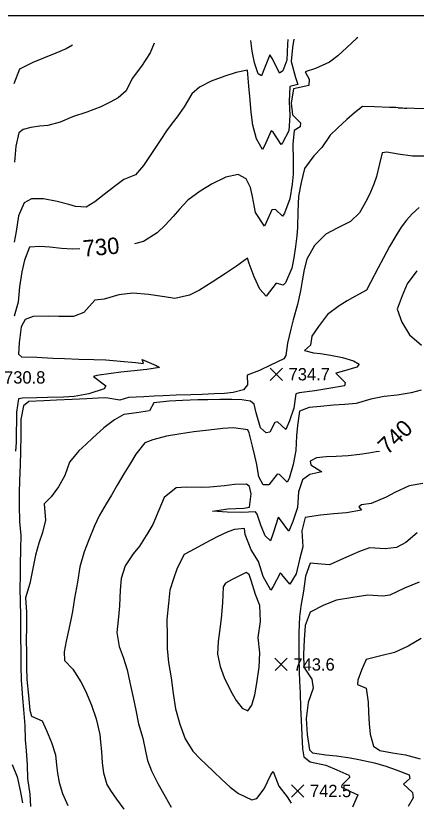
# Model space of a CAD drawing. Extents: x 2566079 to 2571326, y 424054 to 426896.
# Drawn here: x 2570104 to 2570592, y 425917 to 426874 of the extents above; entities that cross this region are included whole.
import ezdxf

# ---------------------------------------------------------------- set-up
doc = ezdxf.new("R2010")
doc.units = 0
for name, color, linetype in [('Contour_ADS_Label_Major', 7, 'Continuous'), ('Contour_ADS_Major', 7, 'Continuous'), ('Contour_ADS_Minor', 7, 'Continuous'), ('Contour_ADS_Spot_Elevation', 7, 'Continuous'), ('Contour_ADS_State_Plane_Border', 7, 'Continuous')]:
    doc.layers.add(name, color=color, linetype=linetype)

# ---------------------------------------------------------------- blocks, each defined once
blk = doc.blocks.new('S750')
at = {"layer": 'Contour_ADS_Spot_Elevation'}
for p, q in [((-0.5, 0.498), (0.5, -0.498)), ((-0.498, -0.5), (0.498, 0.5))]:
    blk.add_line(p, q, dxfattribs=at)

msp = doc.modelspace()

# ---------------------------------------------------------------- linework, layer by layer
at = {"layer": 'Contour_ADS_Major'}
for points in [[(2570520.61, 426847.17), (2570519.03, 426845.86), (2570507.03, 426834.96), (2570496.2, 426825.13), (2570486.28, 426817.4), (2570469.13, 426809.65), (2570456.51, 426805.54), (2570461.22, 426796.51), (2570460.75, 426788.8), (2570442.16, 426784.88), (2570439.63, 426767.36), (2570440.91, 426753.06), (2570450.82, 426743.52), (2570450.24, 426738.77), (2570442.94, 426734.14), (2570441.35, 426717.6), (2570442.02, 426697.77), (2570441.98, 426681.08), (2570440.61, 426668.8), (2570437.85, 426650.87), (2570431.33, 426633.6), (2570428.76, 426629.98), (2570420.45, 426637.81), (2570415.95, 426637.6), (2570409.22, 426622.35), (2570406.82, 426617.78), (2570396.14, 426634.25), (2570392.43, 426653.8), (2570389.93, 426664.76), (2570384.76, 426675.15), (2570375.07, 426680.41), (2570360.06, 426677.47), (2570343.11, 426669.33), (2570328.65, 426660.5), (2570313.86, 426649.16), (2570303.58, 426638.52), (2570295.7, 426629.48), (2570286.12, 426618.95), (2570276.22, 426609.43), (2570259.72, 426599.01), (2570248.64, 426596.14)], [(2570182.24, 426590.11), (2570173.16, 426589.78), (2570160.13, 426590.62), (2570145.89, 426592.02), (2570133.52, 426593.13), (2570120.92, 426592.31), (2570114.9, 426576.21), (2570111.65, 426562.07), (2570108.86, 426543.87), (2570107.12, 426525.37), (2570102.32, 426508.18)], [(2570547.06, 426343.62), (2570542.76, 426343.27), (2570533.8, 426341.53), (2570522.9, 426339.75), (2570508.94, 426338.41), (2570494.22, 426337.5), (2570481.89, 426336.92), (2570470.09, 426336.02), (2570462.72, 426331.75), (2570463.2, 426327.38), (2570476.92, 426318.85), (2570462.07, 426315.68), (2570453.32, 426309.05), (2570448.54, 426294.43), (2570447.15, 426275.55), (2570441.36, 426258.47), (2570436.54, 426246.48), (2570425.42, 426262), (2570423.61, 426263.14), (2570417.53, 426244.39), (2570414.47, 426235.08), (2570407.81, 426240.93), (2570402.44, 426253.94), (2570398, 426267.52), (2570396.23, 426269.98), (2570379.01, 426269.3), (2570361.55, 426269.7), (2570343.64, 426270.81), (2570362.54, 426273.62), (2570381.88, 426274.75), (2570388.81, 426275.65), (2570390.68, 426291.93), (2570388.9, 426301.1), (2570385.09, 426303.89), (2570370.46, 426303.52), (2570358.27, 426301.94), (2570340.32, 426300.27), (2570329.9, 426299.91), (2570311.76, 426300.19), (2570299.55, 426299.34), (2570284.94, 426287.74), (2570278.4, 426272.17), (2570270.95, 426254.91), (2570265.05, 426244.67), (2570255.07, 426228.37), (2570247.29, 426218.95), (2570237.36, 426204.38), (2570232.45, 426189.09), (2570231.41, 426175.04), (2570230.71, 426155.78), (2570229.16, 426142.46), (2570227.41, 426123.19), (2570229.93, 426106.25), (2570235.11, 426093.18), (2570239.69, 426078.14), (2570242.95, 426062.39), (2570247.19, 426044.47), (2570250.35, 426029.05), (2570253.66, 426012.07), (2570259.01, 425994.74), (2570262.54, 425977.01), (2570264.73, 425967.55), (2570269.32, 425955.14), (2570277.03, 425939.66), (2570285.96, 425923.78), (2570293.55, 425910.88)]]:
    msp.add_lwpolyline(points, dxfattribs=at)
at = {"layer": 'Contour_ADS_Minor'}
for points in [[(2570780.48, 426854.17), (2570780.38, 426851.3), (2570779.9, 426837.39), (2570779.42, 426818.72), (2570778.35, 426800.91), (2570772.67, 426783.42), (2570767.53, 426775.59), (2570757.18, 426779.14), (2570751.98, 426773.98), (2570744.94, 426773.59), (2570735.77, 426784.36), (2570728.02, 426795.99), (2570720.41, 426800.62), (2570704.04, 426797.08), (2570686.02, 426794.85), (2570669.4, 426792.1), (2570659.08, 426789.79), (2570648.35, 426787.36), (2570637.98, 426785.03), (2570621.88, 426778.83), (2570613.03, 426761.83), (2570598.23, 426760.6), (2570580.19, 426761.28)], [(2570442.52, 426845.07), (2570441.04, 426834.99), (2570439.57, 426817.88), (2570444.54, 426798.67), (2570447.46, 426790.19), (2570437.86, 426787.58), (2570436.88, 426769.28), (2570437.74, 426752.17), (2570436.59, 426733.56), (2570429.08, 426719), (2570427.12, 426716.95), (2570417.61, 426732.13), (2570414.98, 426733.53), (2570407.12, 426715.49), (2570404.69, 426710.84), (2570397.28, 426723.85), (2570392.81, 426740.69), (2570390.76, 426756.51), (2570389.14, 426775.61), (2570388.07, 426787.85), (2570386.24, 426807.64), (2570372.46, 426804.57), (2570358.57, 426800.25), (2570342.27, 426794.18), (2570327.83, 426786.81), (2570318.48, 426778.65), (2570309.3, 426762.99), (2570300.53, 426750.56), (2570294.71, 426743.14), (2570287.85, 426733.58), (2570280.83, 426723.22), (2570270.48, 426707.23), (2570259.54, 426691.54), (2570249.82, 426680.17), (2570235.75, 426674.41), (2570224.52, 426666.15), (2570211.7, 426656.13), (2570200.53, 426647.49), (2570189.81, 426640.7), (2570177.14, 426641.72), (2570168.73, 426644.07), (2570154.58, 426647.89), (2570138, 426651.11), (2570123.46, 426651.08), (2570114.34, 426646.09), (2570107.66, 426630.11), (2570104.77, 426611.42), (2570102.21, 426598.45)], [(2570435.42, 426844.88), (2570435.09, 426839.11), (2570434.1, 426819.58), (2570429.5, 426806.5), (2570425.28, 426803.83), (2570416.76, 426821.49), (2570413.42, 426826.18), (2570407.18, 426809.76), (2570403.21, 426800.66), (2570399.47, 426803.08), (2570394.63, 426816.33), (2570391.94, 426830.71), (2570390.41, 426843.66)], [(2570173.27, 426837.82), (2570165.59, 426833.65), (2570152.98, 426828.38), (2570138.06, 426822.11), (2570124.93, 426816.66), (2570108.97, 426808.71), (2570101.79, 426791.01)], [(2570272.62, 426840.49), (2570267.91, 426828.44), (2570257.43, 426812.3), (2570245.78, 426797.32), (2570238.81, 426782.38), (2570228.85, 426773.88), (2570218.98, 426768.38), (2570207.68, 426762.88), (2570190.96, 426756.36), (2570173.42, 426750.8), (2570158.35, 426744.1), (2570143.15, 426740.1), (2570133.63, 426739.23), (2570122.77, 426737.77), (2570113.46, 426735.24), (2570107.91, 426731.33), (2570104.36, 426715.06), (2570102.83, 426695.65)], [(2570559.09, 426762.26), (2570541.01, 426763.09), (2570526.16, 426763.33), (2570516.72, 426755.59), (2570507.33, 426747.38), (2570496.35, 426737.53), (2570487.08, 426728.53), (2570476.6, 426713.6), (2570466.9, 426703.37), (2570455.61, 426687.96), (2570451.46, 426670.67), (2570448.29, 426654.24), (2570447.48, 426635.53), (2570447.3, 426616.24), (2570446.22, 426606.1), (2570444.69, 426593.04), (2570442.72, 426579.05), (2570440.28, 426566.67), (2570432.48, 426548.93), (2570429.86, 426545.9), (2570421.17, 426548.43), (2570409.16, 426532.67), (2570401.42, 426541.12), (2570394.32, 426556.1), (2570388.44, 426572.4), (2570386.27, 426578.62), (2570372.82, 426569.12), (2570359.62, 426560.12), (2570343.46, 426549.49), (2570327.86, 426540.03), (2570315.64, 426533.9), (2570297.79, 426529.71), (2570285.15, 426531.78), (2570265.97, 426534.78), (2570246.79, 426536.21), (2570229.91, 426534.03), (2570211.98, 426528.76), (2570200.42, 426527.54), (2570186.98, 426512.88), (2570174.42, 426507.84), (2570156.5, 426507.7), (2570143.85, 426508.08), (2570125.37, 426507.94), (2570115.62, 426504.18), (2570110.9, 426495.12), (2570108.29, 426475.87), (2570107.77, 426461.96), (2570111.32, 426458.86), (2570129.75, 426458.15), (2570149.59, 426457.31), (2570163.69, 426456.72), (2570181.2, 426456.1), (2570199.15, 426455.5), (2570213.76, 426455.01), (2570231.83, 426453.67), (2570249.87, 426451.66), (2570259.56, 426450.52), (2570258.18, 426455.3), (2570275.25, 426448.13), (2570279.33, 426445.85), (2570263.71, 426443.41), (2570244.45, 426441.32), (2570232.33, 426439.97), (2570220.56, 426438.61), (2570203.12, 426436.2), (2570198.92, 426435.02), (2570213.89, 426423.39), (2570211.7, 426419.9), (2570193.3, 426413.92), (2570175.39, 426410.46), (2570162.31, 426409.76), (2570142.75, 426409.18), (2570129.93, 426408.84), (2570112.65, 426408.38), (2570107.43, 426407.7), (2570105.33, 426391.58), (2570105.19, 426380.28), (2570104.94, 426367.04), (2570104.58, 426354.36), (2570104.05, 426343.88)], [(2570604.42, 426702.74), (2570587.09, 426702.97), (2570569.79, 426705.31), (2570555.69, 426707.8), (2570550.24, 426706.75), (2570546.95, 426693.54), (2570543.23, 426678.19), (2570540.12, 426668.94), (2570536.13, 426659.24), (2570531.62, 426649.75), (2570522.63, 426634.07), (2570511.63, 426623.33), (2570495.25, 426615.18), (2570481.65, 426607.94), (2570467.82, 426594.3), (2570458.57, 426577.53), (2570455.3, 426564.96), (2570452.89, 426551.37), (2570450.95, 426539.2), (2570447.14, 426522.58), (2570442, 426503.79), (2570439.13, 426492.42), (2570435.13, 426475.4), (2570433.15, 426460.48), (2570430.45, 426456.36), (2570414.42, 426448.42), (2570400.88, 426441.98), (2570385.7, 426436.48), (2570386.2, 426424.81), (2570381.55, 426418.71), (2570368.7, 426415.19), (2570358.32, 426414.23), (2570345.65, 426413.58), (2570331.32, 426413.06), (2570317.39, 426412.65), (2570299.59, 426412.17), (2570283.63, 426411.41), (2570272.78, 426410.84), (2570260.11, 426410.17), (2570241.61, 426409.19), (2570231.02, 426406.12), (2570213.83, 426408.77), (2570204.37, 426408.37), (2570190.75, 426407.64), (2570172.87, 426406.75), (2570154.04, 426405.86), (2570138.4, 426405.15), (2570120.01, 426404.35), (2570113.79, 426399.19), (2570110.54, 426382.32), (2570110.34, 426363.12), (2570110, 426343.77), (2570109.55, 426327.18), (2570108.67, 426308.39), (2570108.42, 426293.2), (2570108.44, 426277.76), (2570108.87, 426258.36), (2570110.35, 426241.42), (2570110.11, 426225.18), (2570109.68, 426205.29), (2570109.52, 426191.75), (2570109.44, 426178.01), (2570109.56, 426159.93), (2570109.96, 426144.66), (2570110.02, 426134.69), (2570110.16, 426118.15), (2570110.34, 426099.09), (2570110.49, 426082.89), (2570110.86, 426065.25), (2570111.65, 426055.11), (2570112.52, 426043.44), (2570113.55, 426029.8), (2570115.18, 426010.32), (2570115.85, 425992.65), (2570116.94, 425979.77), (2570118.15, 425962.34)], [(2570595.24, 426640.25), (2570586.75, 426632.55), (2570579.65, 426624.94), (2570573.29, 426616.51), (2570566.69, 426606.03), (2570559.21, 426592.88), (2570551.65, 426579), (2570545.15, 426566.93), (2570535.82, 426549.25), (2570531.29, 426539.81), (2570517.04, 426532.08), (2570507.71, 426526.89), (2570497.67, 426520.76), (2570483.86, 426510.19), (2570472.87, 426495.73), (2570464.73, 426483.87), (2570463.12, 426472.89), (2570455.61, 426466.5), (2570466.78, 426463.59), (2570475.31, 426462.71), (2570487.17, 426460.85), (2570501.82, 426457.76), (2570515.12, 426453.88), (2570522.05, 426449.79), (2570519.32, 426446.05), (2570501.53, 426440.73), (2570493.82, 426438.97), (2570505.21, 426427.65), (2570504.17, 426423.43), (2570485.46, 426420.24), (2570468.19, 426417.33), (2570449.25, 426414.75), (2570445.24, 426413.6), (2570442.67, 426396.46), (2570437.57, 426380.74), (2570432.99, 426370.17), (2570422.97, 426379.73), (2570419.75, 426378.99), (2570413.3, 426366.9), (2570408.96, 426366.46), (2570402.14, 426372.32), (2570396.89, 426390.58), (2570394.22, 426401.07), (2570389.87, 426404.98), (2570379.48, 426406.39), (2570367.37, 426406.67), (2570352.5, 426406.68), (2570337.89, 426406.54), (2570325.87, 426406.35), (2570307.24, 426405.77), (2570290.8, 426404.87), (2570272.27, 426402.96), (2570267.2, 426393.03), (2570251.07, 426390.75), (2570235.97, 426388.57), (2570224.56, 426382.11), (2570211.42, 426372.47), (2570197.76, 426359.81), (2570189.8, 426352.65), (2570180.95, 426344.42), (2570169.51, 426330.46), (2570164.14, 426314.23), (2570156.49, 426300.76), (2570147.37, 426288.36), (2570138.8, 426279.72), (2570140.34, 426259.85), (2570136.88, 426244.98), (2570132.25, 426232.18)], [(2570592.2, 426563.46), (2570580.71, 426547.41), (2570574.59, 426533.1), (2570568.58, 426516.82), (2570574.24, 426501.07), (2570583.62, 426485.61), (2570597.95, 426473.04)], [(2570597.82, 426418.23), (2570585.65, 426414.87), (2570568.45, 426411.97), (2570552.65, 426410.48), (2570536.49, 426407.44), (2570518.69, 426401.99), (2570504.92, 426400.85), (2570490.97, 426399.75), (2570475.09, 426398.39), (2570461.53, 426397.06), (2570449.71, 426392.68), (2570446.96, 426375.4), (2570445.93, 426362.7), (2570444.95, 426344.78), (2570441.68, 426327.93), (2570436.93, 426310.72), (2570434.73, 426306.1), (2570425.37, 426315.45), (2570422.31, 426316.09), (2570412.32, 426302.83), (2570405.41, 426302.88), (2570400.15, 426312.61), (2570397.49, 426327.9), (2570395.15, 426338.33), (2570392.46, 426349.93), (2570388.44, 426366.39), (2570386.62, 426369.75), (2570369.09, 426372.23), (2570356.2, 426371.42), (2570339.21, 426369.64), (2570321.02, 426367.35), (2570305.29, 426365.14), (2570287.85, 426362.13), (2570271.22, 426357.76), (2570261.38, 426354.24), (2570250.46, 426340.3), (2570243.81, 426329.55), (2570235.88, 426316.38), (2570227.83, 426302.78), (2570220.61, 426290.43), (2570214.5, 426279.9), (2570205.92, 426265.11), (2570199.96, 426253.26), (2570193.14, 426236.23), (2570187.65, 426221.34), (2570182.4, 426203.25), (2570179.22, 426184.47), (2570175.87, 426164.94), (2570173.47, 426149.08), (2570171.75, 426140.73), (2570168.85, 426127.6), (2570165.65, 426112.69), (2570163.31, 426100.03), (2570163.43, 426089.42), (2570173.63, 426078.95), (2570183.32, 426063.5), (2570189.31, 426052.2), (2570196.27, 426035.09), (2570202.08, 426018.42), (2570206.76, 425999.27), (2570207.58, 425989.89), (2570208.47, 425978.39), (2570209.62, 425964.72), (2570210.93, 425952.56), (2570215.1, 425938.38), (2570219.78, 425931.22), (2570227.08, 425920.76), (2570235.72, 425908.43)], [(2570599.72, 426304.69), (2570583.2, 426301.98), (2570565.43, 426293.65), (2570555.17, 426287.84), (2570536.69, 426280.42), (2570525.02, 426278.77), (2570521.86, 426276.35), (2570525.03, 426272.08), (2570506.7, 426269.08), (2570491.44, 426267.92), (2570475.29, 426266.23), (2570456.38, 426263.16), (2570452.59, 426247.13), (2570453.64, 426227.62), (2570449.57, 426212.32), (2570445.6, 426194.8), (2570437.74, 426182.19), (2570428.17, 426194.03), (2570425.97, 426195.72), (2570417.43, 426179.25), (2570414.71, 426174.86), (2570405.52, 426191.36), (2570399.51, 426209.75), (2570390.68, 426223.96), (2570383.57, 426242.59), (2570382.84, 426249.9), (2570370.39, 426248.79), (2570362.24, 426245.83), (2570349.46, 426239.6), (2570334.82, 426231.86), (2570322.02, 426225.04), (2570309.3, 426218.29), (2570300.67, 426201.56), (2570296.17, 426188.73), (2570291.93, 426175.01), (2570290.05, 426158.71), (2570288.33, 426139.14), (2570288.55, 426119.33), (2570288.52, 426104.05), (2570290.26, 426086.8), (2570293.38, 426068.4), (2570295.79, 426049.23), (2570298.71, 426030.68), (2570303.98, 426011.83), (2570310.55, 425994.12), (2570319.66, 425978.99), (2570329.16, 425969.16)], [(2570592.77, 426244.77), (2570578.85, 426232.9), (2570567.55, 426226.61), (2570553.8, 426225.17), (2570534.96, 426226.28), (2570522.49, 426222.11), (2570513.45, 426217.98), (2570503.09, 426213.25), (2570486.11, 426205.58), (2570471.36, 426206.8), (2570462.71, 426207.52), (2570457.04, 426191.72), (2570454.48, 426173.81), (2570451.07, 426155.58), (2570449.66, 426142.44), (2570448.66, 426123.4), (2570448.76, 426104.33), (2570448.91, 426093.45), (2570449.24, 426075.61), (2570449.65, 426064.22), (2570450.22, 426049.39), (2570450.9, 426031.85), (2570451.5, 426016.74), (2570452.41, 425998.31), (2570453.42, 425981.73), (2570454.77, 425972.03), (2570462.56, 425966.12)], [(2570132.25, 426232.18), (2570128.16, 426217.54), (2570125.02, 426201.3), (2570121.5, 426183.11), (2570116.17, 426165.66), (2570117.31, 426147.91), (2570117.27, 426129.44), (2570117.13, 426114.35), (2570117.19, 426099.11), (2570117.45, 426081.18), (2570117.94, 426066.19), (2570119.7, 426046.85), (2570121.53, 426028.97), (2570123.49, 426021.61), (2570136.42, 426015.8), (2570141.64, 426004.02), (2570147.88, 425989.45), (2570152.83, 425974.64), (2570153.98, 425961.93), (2570154.97, 425952.33), (2570157.06, 425940.69), (2570161.09, 425927.38), (2570167.47, 425913.06)], [(2570595.34, 426184.73), (2570577.27, 426177.28), (2570559.67, 426168.64), (2570550.87, 426167.62), (2570532.57, 426168.9), (2570514.33, 426165.92), (2570494.74, 426162.54), (2570479.22, 426156.59), (2570462.72, 426148.15), (2570456.4, 426132.01), (2570455.33, 426114.35), (2570454.38, 426097.02), (2570454.91, 426081.33), (2570464.69, 426066.57), (2570466.37, 426055.71), (2570460.24, 426038.29), (2570457.54, 426018.82), (2570458.83, 425999.07), (2570461.59, 425980.43), (2570465.61, 425977.07), (2570481.72, 425974.7), (2570494.63, 425973.2), (2570511.09, 425970.91), (2570521.72, 425968.88), (2570540.77, 425964.76), (2570554.47, 425960.73), (2570567.25, 425956.28), (2570583.17, 425950.18), (2570583.66, 425945.82), (2570576.34, 425938.71)], [(2570597.83, 426115.92), (2570581.64, 426106.79), (2570565.18, 426099.18), (2570548.74, 426095.06), (2570530.9, 426090.71), (2570525.1, 426077.61), (2570520.5, 426065.27), (2570520.29, 426060.28), (2570530.88, 426055.7), (2570533.25, 426038.78), (2570533.66, 426026.16), (2570534.54, 426012.09), (2570535.78, 425999.51), (2570539.65, 425985.18), (2570547.42, 425979.7), (2570562.6, 425977.06), (2570578.67, 425974.69), (2570596.34, 425969.84)], [(2570329.16, 425969.16), (2570336.02, 425962.71), (2570344.82, 425954.14), (2570354.89, 425944.46), (2570365.3, 425935.11), (2570375.22, 425927.4), (2570391.7, 425919.92), (2570397.65, 425921.26), (2570406.62, 425933.02), (2570414.5, 425950.04), (2570417.68, 425954.31), (2570424.35, 425936.27), (2570434.62, 425923.57), (2570439.52, 425915.71)], [(2570462.56, 425966.12), (2570481.49, 425961.88), (2570495.01, 425956.19), (2570509.51, 425949.62), (2570510.92, 425947.32), (2570501.23, 425937.52), (2570500.57, 425935.06), (2570517.9, 425927.08), (2570520.7, 425925.78), (2570513.95, 425910.97)], [(2570099.84, 425962.89), (2570105.83, 425947.85), (2570109.56, 425931.2), (2570112.66, 425916.27)], [(2570118.15, 425962.34), (2570118.7, 425945.62), (2570121.38, 425926.74), (2570122.21, 425911.47)], [(2570576.34, 425938.71), (2570587.26, 425928.54), (2570587.85, 425922.07), (2570581.81, 425911.8)]]:
    msp.add_lwpolyline(points, dxfattribs=at)
msp.add_lwpolyline([(2570365.88, 426052), (2570372.5, 426040.77), (2570379.91, 426031.27), (2570386.69, 426028.26), (2570391.73, 426034.88), (2570395.2, 426047.71), (2570397.56, 426061.7), (2570400.36, 426081.12), (2570401.24, 426098.63), (2570399.35, 426117.34), (2570402.05, 426136.75), (2570401.22, 426156.32), (2570396.07, 426169.73), (2570390.59, 426186.53), (2570388.39, 426194.1), (2570384.67, 426196.39), (2570367.7, 426187.8), (2570359.44, 426183.58), (2570356.66, 426179.02), (2570355.87, 426159.46), (2570354.11, 426140.39), (2570352.32, 426124.77), (2570350.65, 426112.54), (2570349.9, 426096.83), (2570352.92, 426081.9), (2570357.82, 426068.49), (2570365.88, 426052)], close=True, dxfattribs=at)
for centre, radius, start, end in [((2569450.73, 402784.74), 24003.12, 87.328175, 87.353386), ((2570682.75, 429083.26), 2324.25, 267.2106, 267.47096)]:
    msp.add_arc(centre, radius, start, end, dxfattribs=at)
at = {"layer": 'Contour_ADS_State_Plane_Border'}
msp.add_lwpolyline([(2566079.33, 424077.11), (2571302.93, 424077.11), (2571302.93, 426873.74), (2566079.33, 426873.74), (2566079.33, 424077.11)], close=True, dxfattribs=at)

# ---------------------------------------------------------------- block references
at = {"layer": 'Contour_ADS_Spot_Elevation', "xscale": 15, "yscale": 15}
for p in [(2570421.32, 426437.59), (2570427.25, 426084.51), (2570447.33, 425930.54)]:
    msp.add_blockref('S750', p, dxfattribs=at)

# ---------------------------------------------------------------- texts
at = {"layer": 'Contour_ADS_Label_Major'}
for s, rotation, p in [('730', 5.18517, (2570186.75, 426580.48)), ('740', 43.332, (2570556.54, 426338.82))]:
    msp.add_text(s, height=20, rotation=rotation, dxfattribs=at).set_placement(p)
at = {"layer": 'Contour_ADS_Spot_Elevation'}
for s, p in [('734.7', (2570436.32, 426430.09)), ('730.8', (2570090.09, 426426.26)), ('743.6', (2570442.25, 426077.01)), ('742.5', (2570462.33, 425923.04))]:
    msp.add_text(s, height=15, dxfattribs=at).set_placement(p)

doc.saveas('drawing.dxf')
